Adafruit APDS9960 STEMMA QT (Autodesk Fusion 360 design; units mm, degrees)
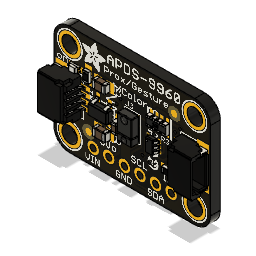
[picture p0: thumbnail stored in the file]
description: Male Header 12x1
sketch "Sketch1" plane through (0, 0, 0) normal (0, 0, 1) x axis (1, 0, 0)
  line L1 (-10.16, 8.89) -> (10.16, 8.89)
  line L2 (-12.7, -6.35) -> (-12.7, 6.35)
  line L3 (10.16, -8.89) -> (-10.16, -8.89)
  line L4 (12.7, 6.35) -> (12.7, -6.35)
  line L5 (11.9561, -8.1461) -> (-11.9561, 8.1461)
  circle C1 centre (-10.16, -6.35) radius 1.25
  circle C2 centre (2.794, -3.81) radius 0.25
  circle C3 centre (-1.905, 2.794) radius 0.25
  circle C4 centre (10.16, -6.35) radius 1.25
  circle C5 centre (1.6637, -3.3441) radius 0.2413
  circle C6 centre (-9.144, -1.651) radius 0.25
  circle C7 centre (-10.16, 6.35) radius 1.25
  circle C8 centre (1.27, -6.35) radius 0.5
  circle C9 centre (6.985, 2.54) radius 0.25
  circle C10 centre (7.786, 3.39) radius 0.25
  circle C11 centre (3.537, 0.508) radius 0.25
  circle C12 centre (-2.159, -3.1623) radius 0.2413
  circle C13 centre (-2.54, 1.778) radius 0.25
  arc A1 centre (10.16, 6.35) radius 2.54 clockwise from (10.16, 8.89) to (12.7, 6.35)
  circle C14 centre (-9.1214, -0.4854) radius 0.25
  circle C15 centre (9.144, 0.381) radius 0.25
  arc A2 centre (10.16, -6.35) radius 2.54 clockwise from (12.7, -6.35) to (10.16, -8.89)
  circle C16 centre (10.16, 6.35) radius 1.25
  circle C17 centre (-1.27, -6.35) radius 0.5
  circle C18 centre (9.398, -1.651) radius 0.25
  circle C19 centre (6.35, -6.35) radius 0.5
  circle C20 centre (-9.144, 2.54) radius 0.25
  circle C21 centre (-3.81, -6.35) radius 0.5
  arc A3 centre (-10.16, 6.35) radius 2.54 clockwise from (-12.7, 6.35) to (-10.16, 8.89)
  arc A4 centre (-10.16, -6.35) radius 2.54 clockwise from (-10.16, -8.89) to (-12.7, -6.35)
  circle C22 centre (-6.35, -6.35) radius 0.5
  circle C23 centre (-9.144, 0.889) radius 0.25
  circle C24 centre (3.81, -6.35) radius 0.5
  point P44 (-11.9561, 8.1461)
  point P45 (11.9561, -8.1461)
  point P46 (0, 0)
  midpoint A3 P44
  midpoint A2 P45
  midpoint L5 P46
extrude "Extrude1" new body sketch "Sketch1" profile of C1 C2 C3 C4 L1 C5 C6 C7 L2 C8 C9 C10 C11 C12 C13 A1 C14 C15 L3 A2 C16 L4 C17 C18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 along normal blind 1.6
decal "Decal1"
decal "Decal2"
base_feature "Base Feature1"
base_feature "Base Feature1"
base_feature "Base Feature1"
base_feature "Base Feature1"
scale "Scale1" ScaleFactor 0.7 named "d1_1"
base_feature "Base Feature1"
base_feature "Base Feature1"
base_feature "Base Feature1"
base_feature "Base Feature1"
base_feature "Base Feature1"
base_feature "Base Feature1"
base_feature "Base Feature1"
base_feature "Base Feature1"
base_feature "Base Feature1" bodies "Header Body"
base_feature "Base Feature1" bodies "Pin"
as_built_joint "As-built1"
as_built_joint "As-built1"
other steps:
create_component "CreateComponent1"
create_component "CreateComponent2"
create_component "CreateComponent3"
create_component "CreateComponent4"
create_component "CreateComponent5"
create_component "CreateComponent6"
create_component "CreateComponent7"
create_component "CreateComponent8"
create_component "CreateComponent1"
create_component "CreateComponent2"
create_component "CreateComponent9"
create_component "CreateComponent10"
create_component "CreateComponent11"
create_component "CreateComponent12"
create_component "CreateComponent13"
create_component "CreateComponent14"
named bodies: "Pin", "Header Body"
